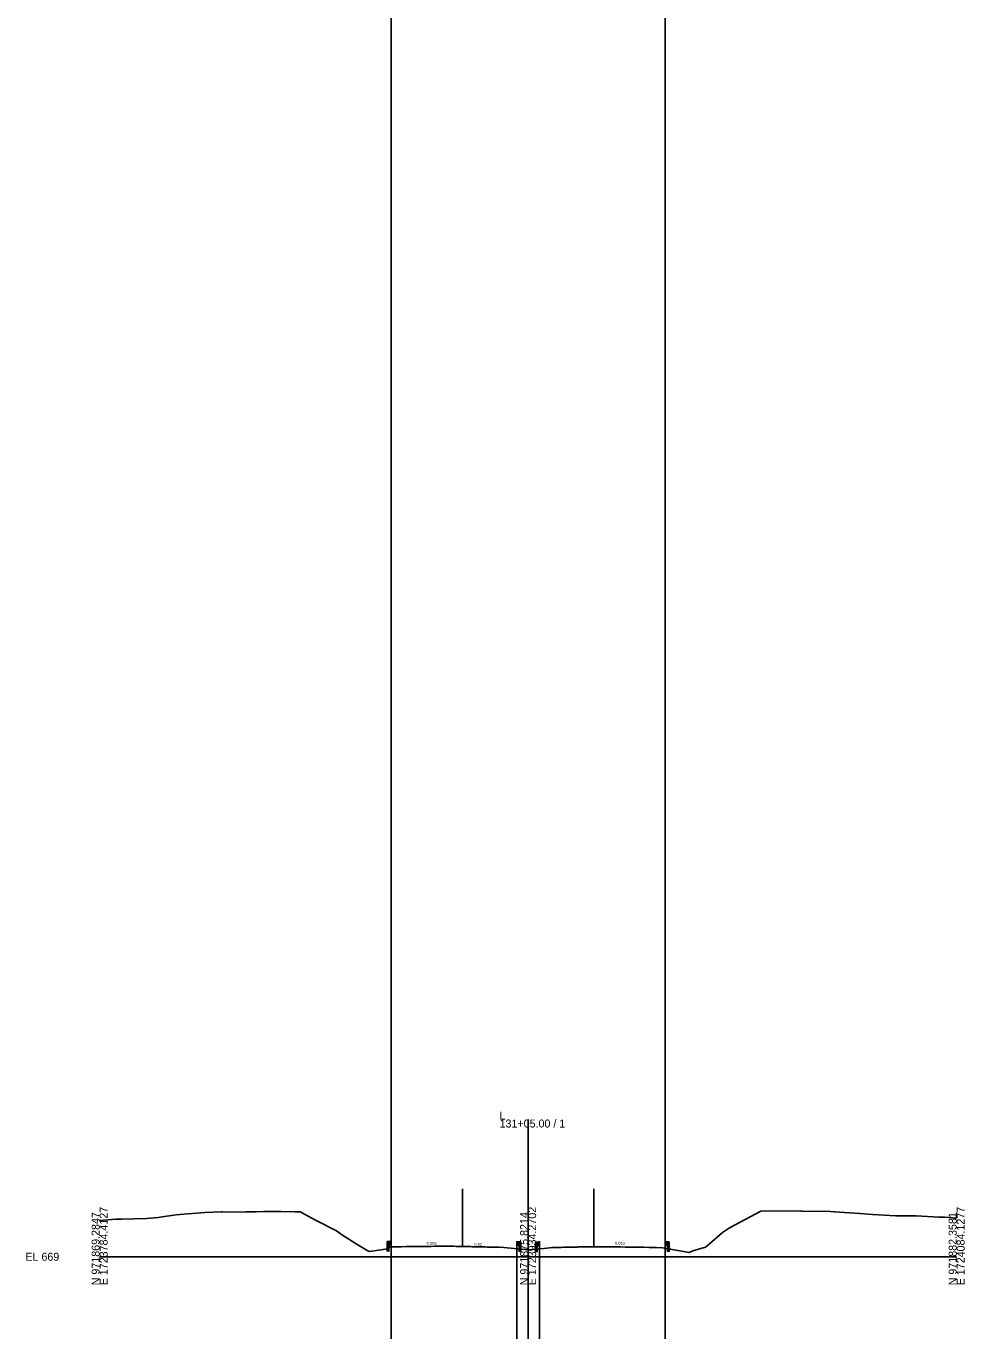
# Model space of a CAD drawing. Extents: x -26 to 303, y -29 to 15026.
# Drawn here: x -25.7 to 302.8, y -28.7 to 430.6 of the extents above; entities that cross this region are included whole.
import ezdxf

# ---------------------------------------------------------------- set-up
doc = ezdxf.new("R2010")
doc.units = 0
for name, color, linetype in [('Exist Cross Section Cell', 7, 'Continuous'), ('Exist XS Center Line Elevation Label', 7, 'Continuous'), ('Exist XS Ground Line', 7, 'Continuous'), ('Prop XS Ditch Standard Text', 7, 'Continuous'), ('Scratch_Level_0', 7, 'Continuous'), ('Typical Guardrail CELL', 7, 'Continuous')]:
    doc.layers.add(name, color=color, linetype=linetype)

msp = doc.modelspace()

# ---------------------------------------------------------------- linework, layer by layer
at = {"layer": 'Exist Cross Section Cell'}
for p, q in [((150, 0), (150, 48.02)), ((0, 0), (150, 0)), ((150, 0), (300, 0))]:
    msp.add_line(p, q, dxfattribs=at)
at = {"layer": 'Exist XS Ground Line'}
msp.add_lwpolyline([(0, 12.65), (5.66, 13.12), (7.73, 13.16), (16.36, 13.42), (20.48, 13.72), (21.89, 13.93), (26.78, 14.69), (30.76, 15.02), (32.55, 15.13), (36.78, 15.46), (42.57, 15.7), (42.94, 15.7), (44.62, 15.64), (51.01, 15.73), (54.55, 15.75), (57.32, 15.79), (60.78, 15.86), (63.39, 15.83), (68.46, 15.73), (70.31, 15.68), (71.52, 14.97), (75.85, 12.63), (82.93, 9.08), (84.7, 7.77), (89.85, 4.51), (93.93, 2.07), (94.45, 1.82), (99.27, 2.57), (100.5, 2.79), (101.85, 3.44), (102.19, 3.44), (102.68, 3.43), (103.22, 3.45), (104.82, 3.48), (105.57, 3.5), (107.3, 3.54), (108.9, 3.56), (109.8, 3.57), (110.41, 3.58), (111.12, 3.59), (111.69, 3.6), (112.3, 3.61), (113.38, 3.62), (114.8, 3.63), (116, 3.64), (117.3, 3.65), (118.62, 3.66), (119.79, 3.67), (120.88, 3.67), (122.28, 3.67), (122.76, 3.67), (123.13, 3.68), (123.97, 3.66), (124.78, 3.64), (126.44, 3.6), (127.29, 3.58), (129.09, 3.55), (129.81, 3.53), (130.46, 3.52), (132.3, 3.48), (134.29, 3.43), (135.05, 3.41), (135.64, 3.39), (136.94, 3.37), (137.29, 3.36), (139.81, 3.3), (141.47, 3.26), (142.71, 3.14), (147.66, 2.65), (150.19, 2.39), (152.46, 2.63), (155.66, 2.94), (158.57, 3.22), (159.01, 3.23), (159.46, 3.24), (159.79, 3.24), (161.61, 3.29), (162.33, 3.31), (163.35, 3.34), (164.6, 3.38), (165.89, 3.39), (167.34, 3.41), (168.84, 3.43), (169.86, 3.45), (170.94, 3.46), (172.35, 3.48), (173.64, 3.49), (174.86, 3.5), (176.68, 3.5), (177.33, 3.5), (178.13, 3.49), (179.85, 3.46), (180.84, 3.45), (182.34, 3.43), (183.99, 3.4), (184.83, 3.39), (185.62, 3.38), (187.33, 3.35), (188, 3.35), (189.5, 3.33), (190.43, 3.3), (192.36, 3.25), (194.52, 3.2), (194.87, 3.19), (197.01, 3.11), (197.63, 2.97), (199.52, 2.68), (199.97, 2.62), (200.41, 2.52), (206.35, 1.43), (207.68, 2.07), (212.05, 3.4), (213.5, 4.55), (218.09, 8.48), (220.17, 9.88), (222.29, 11.04), (231.41, 15.96), (233.34, 16.01), (245.41, 15.95), (245.93, 15.95), (255.83, 15.79), (257.27, 15.71), (266.12, 15.19), (270.49, 14.83), (278.73, 14.33), (284.57, 14.3), (285.86, 14.26), (293.78, 13.86), (295.87, 13.8), (300, 13.55)], dxfattribs=at)
at = {"layer": 'Scratch_Level_0'}
for p, q in [((102, 15009.56), (102, -28.7)), ((198, 15009.56), (198, -28.7)), ((127, 3.59), (127, 23.82)), ((173, 3.48), (173, 23.82)), ((146.07, 5.49), (146.07, -28.7)), ((153.93, 5.49), (153.93, -28.7)), ((122.28, 3.67), (110.41, 3.58)), ((122.28, 3.67), (136.94, 3.37)), ((150, 0), (150, -28.7)), ((173, 3.48), (161.61, 3.29)), ((173, 3.48), (189.5, 3.33))]:
    msp.add_line(p, q, dxfattribs=at)
at = {"layer": 'Typical Guardrail CELL'}
for p, q in [((101.18, 5.36), (100.68, 5.36)), ((100.68, 5.36), (100.68, 2.87)), ((101.18, 5.36), (101.18, 2.87)), ((101.18, 5.36), (101.68, 5.36)), ((101.68, 5.36), (101.68, 4.2)), ((101.68, 5.36), (101.97, 5.16)), ((101.68, 4.83), (101.97, 5.03)), ((101.68, 4.78), (101.68, 4.83)), ((101.68, 4.78), (101.68, 4.73)), ((101.68, 4.73), (101.97, 4.53)), ((146.39, 5.16), (146.1, 4.96)), ((146.39, 4.63), (146.1, 4.83)), ((146.89, 5.16), (146.39, 5.16)), ((146.39, 5.16), (146.39, 4)), ((146.39, 4.58), (146.39, 4.63)), ((146.89, 5.16), (146.89, 2.67)), ((146.89, 5.16), (147.39, 5.16)), ((147.39, 5.16), (147.39, 2.67)), ((153.11, 5.13), (152.61, 5.13)), ((152.61, 5.13), (152.61, 2.64)), ((153.11, 5.13), (153.11, 2.64)), ((153.11, 5.13), (153.61, 5.13)), ((153.61, 5.13), (153.61, 3.97)), ((153.61, 5.13), (153.9, 4.93)), ((153.61, 4.6), (153.9, 4.8)), ((153.61, 4.55), (153.61, 4.6)), ((198.32, 5.2), (198.03, 5)), ((198.32, 4.67), (198.03, 4.87)), ((198.82, 5.2), (198.32, 5.2)), ((198.32, 5.2), (198.32, 4.04)), ((198.32, 4.62), (198.32, 4.67)), ((198.32, 4.62), (198.32, 4.57)), ((198.82, 5.2), (198.82, 2.71)), ((198.82, 5.2), (199.32, 5.2)), ((199.32, 5.2), (199.32, 2.71)), ((101.18, 2.87), (100.68, 2.87)), ((100.68, 2.87), (100.68, 1.86)), ((101.18, 4.2), (101.68, 4.2)), ((101.18, 2.87), (101.18, 1.86)), ((101.68, 4.2), (101.97, 4.4)), ((146.39, 4.53), (146.1, 4.33)), ((146.39, 4), (146.1, 4.2)), ((146.39, 4.58), (146.39, 4.53)), ((146.89, 4), (146.39, 4)), ((146.89, 2.67), (147.39, 2.67)), ((146.89, 2.67), (146.89, 1.67)), ((147.39, 2.67), (147.39, 1.67)), ((153.11, 2.64), (152.61, 2.64)), ((152.61, 2.64), (152.61, 1.64)), ((153.11, 3.97), (153.61, 3.97)), ((153.11, 2.64), (153.11, 1.64)), ((153.61, 4.55), (153.61, 4.5)), ((153.61, 4.5), (153.9, 4.3)), ((153.61, 3.97), (153.9, 4.17)), ((198.32, 4.57), (198.03, 4.37)), ((198.32, 4.04), (198.03, 4.24)), ((198.82, 4.04), (198.32, 4.04)), ((198.82, 2.71), (199.32, 2.71)), ((198.82, 2.71), (198.82, 1.71)), ((199.32, 2.71), (199.32, 1.71))]:
    msp.add_line(p, q, dxfattribs=at)
for centre, start, end in [((101.92, 5.09), 304.9888, 54.997), ((146.15, 4.89), 125.003, 235.0112), ((153.85, 4.86), 304.9888, 54.997), ((198.08, 4.93), 125.003, 235.0112), ((101.92, 4.47), 304.9634, 54.9941), ((146.15, 4.27), 125.0059, 235.0366), ((153.85, 4.24), 304.9634, 54.9941), ((198.08, 4.31), 125.0059, 235.0366)]:
    msp.add_arc(centre, 0.0776, start, end, dxfattribs=at)

# ---------------------------------------------------------------- texts
at = {"layer": 'Exist Cross Section Cell'}
for s, p in [('L', (140, 48.02)), ('131+05.00 / 1', (140, 45.22)), ('EL 669', (-26, -1.4))]:
    msp.add_text(s, height=2.8, dxfattribs=at).set_placement(p)
for s, p in [('N 971869.2847', (0, -10)), ('E 1723784.4127', (2.8, -10)), ('N 971875.8214', (150, -10)), ('E 1723934.2702', (152.8, -10)), ('N 971882.3581', (300, -10)), ('E 1724084.1277', (302.8, -10))]:
    msp.add_text(s, height=2.8, rotation=90, dxfattribs=at).set_placement(p)
at = {"layer": 'Exist XS Center Line Elevation Label'}
msp.add_text('671.41', height=0.18, dxfattribs=at).set_placement((149.67, 1.92))
at = {"layer": 'Prop XS Ditch Standard Text'}
for s, rotation, p in [('0.008', 0.4381, (114.47, 4.18)), ('0.02', 358.7995, (131.17, 3.84)), ('0.010', 359.452, (180.38, 4.24))]:
    msp.add_text(s, height=1, rotation=rotation, dxfattribs=at).set_placement(p)

doc.saveas('drawing.dxf')
